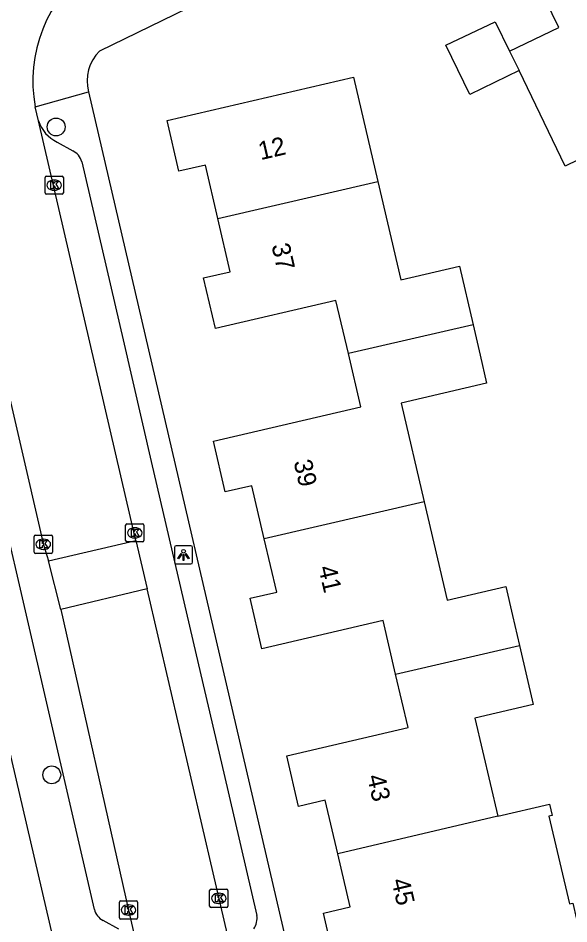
# Model space of a CAD drawing. Extents: x 163427 to 164190, y 380331 to 381641.
# Drawn here: x 163570.7 to 163600.88, y 381284.84 to 381334.51 of the extents above; entities that cross this region are included whole.
import ezdxf

# ---------------------------------------------------------------- set-up
doc = ezdxf.new("R2010")
doc.units = 0
for name, color, linetype in [('IMGEO_Boom', 7, 'Continuous'), ('IMGEO_Kolk', 7, 'Continuous'), ('IMGEO_Lichtpunt', 7, 'Continuous'), ('IMGEO_Pand', 7, 'Continuous'), ('IMGEO_Pand_nummerreeks', 7, 'Continuous'), ('IMGEO_Rijbaan_lokaal_open', 7, 'Continuous'), ('IMGEO_Voetpad_open', 7, 'Continuous')]:
    doc.layers.add(name, color=color, linetype=linetype)

msp = doc.modelspace()

# ---------------------------------------------------------------- linework, layer by layer
at = {"layer": 'IMGEO_Boom'}
for centre in [(163572.779, 381328.536), (163572.539, 381293.009)]:
    msp.add_circle(centre, 0.489, dxfattribs=at)
at = {"layer": 'IMGEO_Kolk'}
for p, q in [((163572.175, 381324.919), (163572.175, 381325.771)), ((163572.25, 381325.845), (163573.102, 381325.845)), ((163573.176, 381325.771), (163573.176, 381324.919)), ((163572.663, 381325.625), (163572.688, 381325.625)), ((163573.102, 381324.845), (163572.25, 381324.845)), ((163572.686, 381325.065), (163572.661, 381325.065)), ((163576.588, 381305.852), (163576.588, 381306.704)), ((163576.663, 381306.778), (163577.515, 381306.778)), ((163577.076, 381306.558), (163577.101, 381306.558)), ((163577.589, 381306.704), (163577.589, 381305.852)), ((163571.574, 381305.227), (163571.574, 381306.079)), ((163571.649, 381306.153), (163572.501, 381306.153)), ((163572.062, 381305.933), (163572.087, 381305.933)), ((163572.575, 381306.079), (163572.575, 381305.227)), ((163577.099, 381305.998), (163577.074, 381305.998)), ((163572.085, 381305.373), (163572.06, 381305.373)), ((163577.515, 381305.778), (163576.663, 381305.778)), ((163572.501, 381305.153), (163571.649, 381305.153)), ((163581.193, 381285.812), (163581.193, 381286.664)), ((163581.268, 381286.738), (163582.12, 381286.738)), ((163581.681, 381286.518), (163581.706, 381286.518)), ((163582.194, 381286.664), (163582.194, 381285.812)), ((163576.246, 381285.17), (163576.246, 381286.022)), ((163576.321, 381286.096), (163577.173, 381286.096)), ((163577.247, 381286.022), (163577.247, 381285.17)), ((163581.704, 381285.958), (163581.679, 381285.958)), ((163576.734, 381285.876), (163576.759, 381285.876)), ((163582.12, 381285.738), (163581.268, 381285.738)), ((163577.173, 381285.096), (163576.321, 381285.096)), ((163576.757, 381285.316), (163576.732, 381285.316))]:
    msp.add_line(p, q, dxfattribs=at)
for points in [[(163572.175, 381324.919), (163572.175, 381325.771)], [(163572.25, 381325.845), (163573.102, 381325.845)], [(163573.176, 381325.771), (163573.176, 381324.919)], [(163572.496, 381325.545), (163572.619, 381325.545), (163572.619, 381325.394), (163572.749, 381325.545), (163572.913, 381325.545), (163572.767, 381325.394), (163572.92, 381325.145), (163572.768, 381325.145), (163572.683, 381325.309), (163572.619, 381325.242), (163572.619, 381325.145), (163572.496, 381325.145), (163572.496, 381325.545)], [(163573.102, 381324.845), (163572.25, 381324.845)], [(163576.588, 381305.852), (163576.588, 381306.704)], [(163576.663, 381306.778), (163577.515, 381306.778)], [(163576.909, 381306.478), (163577.032, 381306.478), (163577.032, 381306.327), (163577.162, 381306.478), (163577.326, 381306.478), (163577.18, 381306.327), (163577.333, 381306.078), (163577.181, 381306.078), (163577.096, 381306.242), (163577.032, 381306.175), (163577.032, 381306.078), (163576.909, 381306.078), (163576.909, 381306.478)], [(163577.589, 381306.704), (163577.589, 381305.852)], [(163571.574, 381305.227), (163571.574, 381306.079)], [(163571.649, 381306.153), (163572.501, 381306.153)], [(163571.895, 381305.853), (163572.018, 381305.853), (163572.018, 381305.702), (163572.148, 381305.853), (163572.312, 381305.853), (163572.166, 381305.702), (163572.319, 381305.453), (163572.167, 381305.453), (163572.082, 381305.617), (163572.018, 381305.55), (163572.018, 381305.453), (163571.895, 381305.453), (163571.895, 381305.853)], [(163572.575, 381306.079), (163572.575, 381305.227)], [(163577.515, 381305.778), (163576.663, 381305.778)], [(163572.501, 381305.153), (163571.649, 381305.153)], [(163581.193, 381285.812), (163581.193, 381286.664)], [(163581.268, 381286.738), (163582.12, 381286.738)], [(163582.194, 381286.664), (163582.194, 381285.812)], [(163576.246, 381285.17), (163576.246, 381286.022)], [(163576.321, 381286.096), (163577.173, 381286.096)], [(163577.247, 381286.022), (163577.247, 381285.17)], [(163581.514, 381286.438), (163581.637, 381286.438), (163581.637, 381286.287), (163581.767, 381286.438), (163581.931, 381286.438), (163581.785, 381286.287), (163581.938, 381286.038), (163581.786, 381286.038), (163581.701, 381286.202), (163581.637, 381286.135), (163581.637, 381286.038), (163581.514, 381286.038), (163581.514, 381286.438)], [(163576.567, 381285.796), (163576.69, 381285.796), (163576.69, 381285.645), (163576.82, 381285.796), (163576.984, 381285.796), (163576.838, 381285.645), (163576.991, 381285.396), (163576.839, 381285.396), (163576.754, 381285.56), (163576.69, 381285.493), (163576.69, 381285.396), (163576.567, 381285.396), (163576.567, 381285.796)], [(163582.12, 381285.738), (163581.268, 381285.738)], [(163577.173, 381285.096), (163576.321, 381285.096)]]:
    msp.add_lwpolyline(points, dxfattribs=at)
for centre, start, end in [((163572.252, 381325.769), 91.552, 178.448), ((163572.252, 381325.769), 91.552, 178.448), ((163573.1, 381325.769), 1.552, 88.448), ((163573.1, 381325.769), 1.552, 88.448), ((163572.252, 381324.921), 181.552, 268.448), ((163572.252, 381324.921), 181.552, 268.448), ((163573.1, 381324.921), 271.552, 358.448), ((163573.1, 381324.921), 271.552, 358.448), ((163576.665, 381306.702), 91.552, 178.448), ((163576.665, 381306.702), 91.552, 178.448), ((163577.513, 381306.702), 1.552, 88.448), ((163577.513, 381306.702), 1.552, 88.448), ((163571.651, 381306.077), 91.552, 178.448), ((163571.651, 381306.077), 91.552, 178.448), ((163572.499, 381306.077), 1.552, 88.448), ((163572.499, 381306.077), 1.552, 88.448), ((163576.665, 381305.854), 181.552, 268.448), ((163576.665, 381305.854), 181.552, 268.448), ((163577.513, 381305.854), 271.552, 358.448), ((163577.513, 381305.854), 271.552, 358.448), ((163571.651, 381305.229), 181.552, 268.448), ((163571.651, 381305.229), 181.552, 268.448), ((163572.499, 381305.229), 271.552, 358.448), ((163572.499, 381305.229), 271.552, 358.448), ((163581.27, 381286.662), 91.552, 178.448), ((163581.27, 381286.662), 91.552, 178.448), ((163582.118, 381286.662), 1.552, 88.448), ((163582.118, 381286.662), 1.552, 88.448), ((163576.323, 381286.02), 91.552, 178.448), ((163576.323, 381286.02), 91.552, 178.448), ((163577.171, 381286.02), 1.552, 88.448), ((163577.171, 381286.02), 1.552, 88.448), ((163581.27, 381285.814), 181.552, 268.448), ((163581.27, 381285.814), 181.552, 268.448), ((163582.118, 381285.814), 271.552, 358.448), ((163582.118, 381285.814), 271.552, 358.448), ((163576.323, 381285.172), 181.552, 268.448), ((163576.323, 381285.172), 181.552, 268.448), ((163577.171, 381285.172), 271.552, 358.448), ((163577.171, 381285.172), 271.552, 358.448)]:
    msp.add_arc(centre, 0.0765, start, end, dxfattribs=at)
for centre, major_axis, ratio, start_param, end_param in [((163572.662, 381325.345), (-0.387, 0.002), 0.722429, 4.712389, 7.853982), ((163572.687, 381325.345), (-0.39, 0.002), 0.717154, 1.570796, 4.712389), ((163577.075, 381306.278), (-0.387, 0.002), 0.722429, 4.712389, 7.853982), ((163577.1, 381306.278), (-0.39, 0.002), 0.717154, 1.570796, 4.712389), ((163572.061, 381305.653), (-0.387, 0.002), 0.722429, 4.712389, 7.853982), ((163572.086, 381305.653), (-0.39, 0.002), 0.717154, 1.570796, 4.712389), ((163581.68, 381286.238), (-0.387, 0.002), 0.722429, 4.712389, 7.853982), ((163581.705, 381286.238), (-0.39, 0.002), 0.717154, 1.570796, 4.712389), ((163576.733, 381285.596), (-0.387, 0.002), 0.722429, 4.712389, 7.853982), ((163576.758, 381285.596), (-0.39, 0.002), 0.717154, 1.570796, 4.712389)]:
    msp.add_ellipse(centre, major_axis=major_axis, ratio=ratio, start_param=start_param, end_param=end_param, dxfattribs=at)
at = {"layer": 'IMGEO_Lichtpunt'}
for p, q in [((163579.263, 381305.475), (163579.263, 381304.668)), ((163579.263, 381305.475), (163579.263, 381304.668)), ((163580.165, 381305.57), (163579.357, 381305.57)), ((163580.165, 381305.57), (163579.357, 381305.57)), ((163580.259, 381304.668), (163580.259, 381305.475)), ((163580.259, 381304.668), (163580.259, 381305.475)), ((163579.357, 381304.574), (163580.165, 381304.574)), ((163579.357, 381304.574), (163580.165, 381304.574))]:
    msp.add_line(p, q, dxfattribs=at)
for points in [[(163579.637, 381305.139), (163579.676, 381305.111), (163579.488, 381304.849), (163579.45, 381304.876), (163579.637, 381305.139)], [(163579.739, 381305.091), (163579.786, 381305.091), (163579.786, 381304.769), (163579.739, 381304.769), (163579.739, 381305.091)], [(163579.849, 381305.111), (163579.887, 381305.138), (163580.074, 381304.876), (163580.035, 381304.848), (163579.849, 381305.111)]]:
    msp.add_lwpolyline(points, dxfattribs=at)
msp.add_circle((163579.762, 381305.273), 0.0994, dxfattribs=at)
for centre, start, end in [((163579.357, 381305.475), 90, 180), ((163579.357, 381305.475), 90, 180), ((163580.165, 381305.475), 0, 90), ((163580.165, 381305.475), 0, 90), ((163579.357, 381304.668), 180, 270), ((163579.357, 381304.668), 180, 270), ((163580.165, 381304.668), 270, 0), ((163580.165, 381304.668), 270, 360)]:
    msp.add_arc(centre, 0.0946, start, end, dxfattribs=at)
at = {"layer": 'IMGEO_Pand'}
for points in [[(163597.625, 381332.689), (163600.326, 381333.998), (163597.36, 381340.12), (163599.9, 381341.37), (163600.558, 381340.025), (163603.253, 381341.342)], [(163598.149, 381331.624), (163595.447, 381330.317), (163594.14, 381333.02), (163596.84, 381334.31), (163597.625, 381332.689)], [(163597.625, 381332.689), (163598.149, 381331.624)], [(163607.829, 381331.883), (163608.59, 381330.244), (163603.63, 381327.83), (163600.68, 381326.39), (163598.149, 381331.624)], [(163581.648, 381323.521), (163580.973, 381326.448), (163579.51, 381326.11), (163578.86, 381328.89), (163589.07, 381331.26), (163590.407, 381325.55)], [(163581.648, 381323.521), (163590.407, 381325.55)], [(163590.407, 381325.55), (163591.673, 381320.147), (163594.89, 381320.9), (163595.629, 381317.695)], [(163588.796, 381316.109), (163588.118, 381319.019), (163581.51, 381317.48), (163580.86, 381320.26), (163582.323, 381320.598), (163581.648, 381323.521)], [(163595.629, 381317.695), (163588.796, 381316.109)], [(163595.629, 381317.695), (163596.013, 381316.028), (163596.37, 381314.48), (163591.696, 381313.39), (163592.956, 381307.985)], [(163584.187, 381305.951), (163583.508, 381308.86), (163582.05, 381308.52), (163581.41, 381311.31), (163589.476, 381313.188), (163588.796, 381316.109)], [(163592.956, 381307.985), (163584.187, 381305.951)], [(163592.956, 381307.985), (163594.216, 381302.581), (163597.43, 381303.33), (163597.799, 381301.741), (163598.181, 381300.094)], [(163591.388, 381298.531), (163590.702, 381301.47), (163584.06, 381299.92), (163583.41, 381302.69), (163584.868, 381303.03), (163584.187, 381305.951)], [(163591.388, 381298.531), (163598.181, 381300.094)], [(163598.181, 381300.094), (163598.93, 381296.87), (163595.734, 381296.124), (163596.991, 381290.736)], [(163588.216, 381288.682), (163587.53, 381291.612), (163586.07, 381291.27), (163585.43, 381294.05), (163592.072, 381295.6), (163591.388, 381298.531)], [(163596.991, 381290.736), (163599.826, 381291.4), (163599.972, 381290.776), (163599.791, 381290.734), (163600.912, 381285.927), (163601.092, 381285.969), (163601.704, 381283.347), (163595.705, 381281.948), (163595.156, 381284.302), (163588.07, 381282.65), (163587.44, 381285.42), (163588.9, 381285.762), (163588.216, 381288.682)], [(163596.991, 381290.736), (163588.216, 381288.682)]]:
    msp.add_lwpolyline(points, dxfattribs=at)
at = {"layer": 'IMGEO_Rijbaan_lokaal_open'}
for points in [[(163571.811, 381328.872), (163571.631, 381329.632)], [(163577.154, 381305.862), (163571.811, 381328.872)], [(163567.201, 381326.721), (163567.904, 381323.7), (163572.087, 381305.625), (163572.362, 381304.745)], [(163572.362, 381304.745), (163577.154, 381305.862)], [(163577.154, 381305.862), (163577.769, 381303.212)], [(163573.028, 381302.074), (163572.362, 381304.745)], [(163577.769, 381303.212), (163573.028, 381302.074)], [(163582.593, 381282.442), (163577.769, 381303.212)], [(163573.028, 381302.074), (163576.744, 381285.596), (163577.254, 381283.368)]]:
    msp.add_lwpolyline(points, dxfattribs=at)
msp.add_arc((163579.233, 381331.054), 7.734, 126.2232, 190.5924, dxfattribs=at)
at = {"layer": 'IMGEO_Voetpad_open'}
for points in [[(163661.825, 381374.917), (163575.154, 381332.697)], [(163571.631, 381329.632), (163574.547, 381330.467)], [(163574.547, 381330.467), (163586.109, 381280.708)], [(163572.835, 381327.711), (163573.688, 381327.228)], [(163574.183, 381326.627), (163576.449, 381316.864), (163577.997, 381310.193), (163580.587, 381299.038), (163581.966, 381293.094), (163583.775, 381285.302)], [(163574.878, 381285.631), (163566.07, 381323.69)], [(163569.929, 381295.551), (163573.656, 381279.496), (163569.808, 381264.93), (163571.382, 381253.255)], [(163576.207, 381284.549), (163575.348, 381285.014)]]:
    msp.add_lwpolyline(points, dxfattribs=at)
for centre, radius, start, end in [((163576.821, 381331.046), 2.347, 135.2758, 194.2705), ((163573.682, 381329.49), 1.971, 198.2855, 244.539), ((163573.282, 381326.389), 0.932, 14.7842, 64.1674), ((163575.8, 381285.846), 0.946, 193.1085, 241.4882), ((163582.878, 381285.122), 0.915, 322.9316, 11.3652)]:
    msp.add_arc(centre, radius, start, end, dxfattribs=at)

# ---------------------------------------------------------------- texts
at = {"layer": 'IMGEO_Pand_nummerreeks'}
for s, rotation, p in [('12', 13.0684, (163583.987, 381326.713)), ('37', 282.9946, (163584.576, 381322.042)), ('39', 283.1309, (163585.788, 381310.178)), ('41', 283.1309, (163587.142, 381304.374)), ('43', 283.1805, (163589.812, 381292.919)), ('45', 283.1778, (163591.147, 381287.221))]:
    msp.add_text(s, height=1, rotation=rotation, dxfattribs=at).set_placement(p)

doc.saveas('drawing.dxf')
